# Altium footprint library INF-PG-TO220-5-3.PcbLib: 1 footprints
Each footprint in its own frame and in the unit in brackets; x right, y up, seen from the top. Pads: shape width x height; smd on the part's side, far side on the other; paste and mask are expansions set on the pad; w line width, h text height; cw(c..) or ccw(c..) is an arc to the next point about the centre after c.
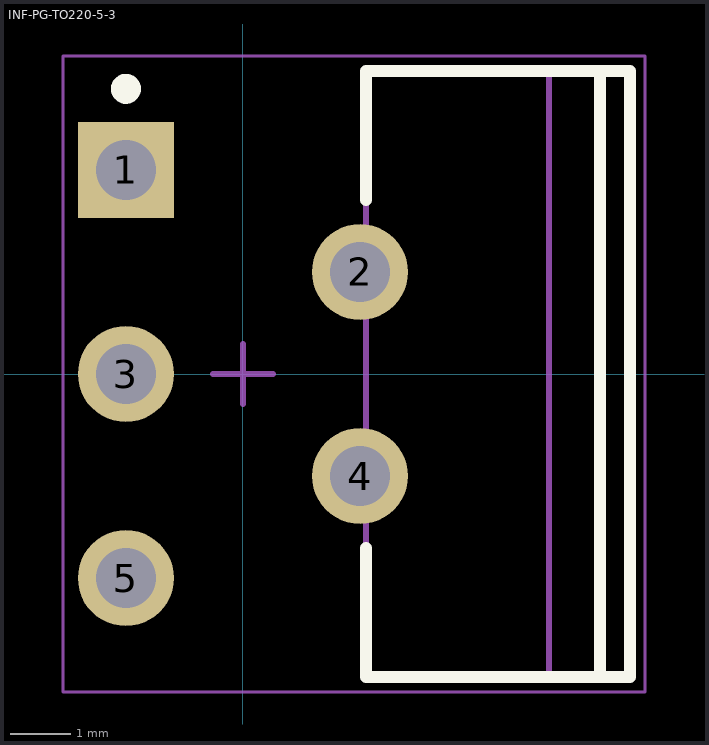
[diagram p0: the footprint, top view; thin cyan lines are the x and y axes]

## INF-PG-TO220-5-3 [mm] "FM, 5-Leads, Body 9.9x4.4mm, Pitch 1.7mm"
height 19.57
pads (5):
  rect 1.6x1.6 hole 1: 1(-1.95,3.4)
  round 1.6 hole 1: 2(1.95,1.7) 3(-1.95,0) 4(1.95,-1.7) 5(-1.95,-3.4)
Top Overlay:
  circle w0.25: c-1.95,4.75 r0.125
  lines w0.2: 2.05,-2.9 2.05,-5.05 6.45,-5.05 6.45,5.05 2.05,5.05 2.05,2.9 ; 5.95,-5.05 5.95,5.05
Mechanical 13:
  lines w0.1: 5.1,-5.05 5.1,5.05 ; 2.05,-5.05 6.45,-5.05 6.45,5.05 2.05,5.05 2.05,-5.05
Mechanical 15:
  lines w0.05: -3,-5.3 6.7,-5.3 6.7,5.3 -3,5.3 -3,-5.3
  lines w0.1: -0.5,0 0.5,0 ; 0,-0.5 0,0.5
3D body: height 19.57, standoff 18.6, extent 5.1,-4.95 6.45,4.95
3D body: height 17.13, standoff 16.77, extent 5.1,-4.95 6.45,-1.825
3D body: height 17.13, standoff 16.77, extent 5.1,1.825 6.45,4.95
3D body: height 16.77, standoff 16.41, extent 5.1,-4.95 6.45,-1.825
3D body: height 16.77, standoff 16.41, extent 5.1,1.825 6.45,4.95
3D body: height 17.47, standoff 17.13, extent 5.1,-4.95 6.45,-1.79
3D body: height 17.47, standoff 17.13, extent 5.1,1.79 6.45,4.95
3D body: height 16.42, standoff 16.07, extent 5.1,-4.95 6.45,-1.79
3D body: height 16.42, standoff 16.07, extent 5.1,1.79 6.45,4.95
3D body: height 17.79, standoff 17.47, extent 5.1,-4.95 6.45,-1.686
3D body: height 17.79, standoff 17.47, extent 5.1,1.686 6.45,4.95
3D body: height 16.08, standoff 15.76, extent 5.1,-4.95 6.45,-1.686
3D body: height 16.08, standoff 15.76, extent 5.1,1.686 6.45,4.95
3D body: height 18.07, standoff 17.78, extent 5.1,-4.95 6.45,-1.517
3D body: height 18.07, standoff 17.78, extent 5.1,1.517 6.45,4.95
3D body: height 15.76, standoff 15.48, extent 5.1,-4.95 6.45,-1.517
3D body: height 15.76, standoff 15.48, extent 5.1,1.517 6.45,4.95
3D body: height 18.29, standoff 18.06, extent 5.1,-4.95 6.45,-1.29
3D body: height 18.29, standoff 18.06, extent 5.1,1.29 6.45,4.95
3D body: height 15.48, standoff 15.25, extent 5.1,-4.95 6.45,-1.29
3D body: height 15.48, standoff 15.25, extent 5.1,1.29 6.45,4.95
3D body: height 18.46, standoff 18.29, extent 5.1,-4.95 6.45,-1.014
3D body: height 18.46, standoff 18.29, extent 5.1,1.014 6.45,4.95
3D body: height 15.26, standoff 15.08, extent 5.1,-4.95 6.45,-1.014
3D body: height 15.26, standoff 15.08, extent 5.1,1.014 6.45,4.95
3D body: height 18.56, standoff 18.46, extent 5.1,-4.95 6.45,-0.698
3D body: height 18.56, standoff 18.46, extent 5.1,0.698 6.45,4.95
3D body: height 15.09, standoff 14.98, extent 5.1,-4.95 6.45,-0.698
3D body: height 15.09, standoff 14.98, extent 5.1,0.698 6.45,4.95
3D body: height 18.6, standoff 18.56, extent 5.1,-4.95 6.45,-0.356
3D body: height 18.6, standoff 18.56, extent 5.1,0.356 6.45,4.95
3D body: height 14.99, standoff 14.95, extent 5.1,-4.95 6.45,-0.356
3D body: height 14.99, standoff 14.95, extent 5.1,0.356 6.45,4.95
3D body: height 14.95, standoff 13.17, extent 5.1,-4.95 6.45,4.95
3D body: height 13.17, standoff 1.47, extent 2.05,-5.05 6.45,5.05
3D body: height 0, standoff -1.6, extent -2.2,-3.8 -1.7,-3
3D body: height 1.47, standoff 0.99, extent 4,-3.95 4.5,-2.85
3D body: height 0.99, standoff 0.49, extent -2.2,-3.95 4.5,-2.85
3D body: height 0.49, standoff 0, extent -2.2,-3.95 -1.7,-2.85
3D body: height 0, standoff -1.6, extent 1.7,-2.1 2.2,-1.3
3D body: height 1.47, standoff 0.99, extent 4,-2.25 4.5,-1.15
3D body: height 0.99, standoff 0.49, extent 1.7,-2.25 4.5,-1.15
3D body: height 0.49, standoff 0, extent 1.7,-2.25 2.2,-1.15
3D body: height 0, standoff -1.6, extent -2.2,-0.4 -1.7,0.4
3D body: height 1.47, standoff 0.99, extent 4,-0.55 4.5,0.55
3D body: height 0.99, standoff 0.49, extent -2.2,-0.55 4.5,0.55
3D body: height 0.49, standoff 0, extent -2.2,-0.55 -1.7,0.55
3D body: height 0, standoff -1.6, extent 1.7,1.3 2.2,2.1
3D body: height 1.47, standoff 0.99, extent 4,1.15 4.5,2.25
3D body: height 0.99, standoff 0.49, extent 1.7,1.15 4.5,2.25
3D body: height 0.49, standoff 0, extent 1.7,1.15 2.2,2.25
3D body: height 0, standoff -1.6, extent -2.2,3 -1.7,3.8
3D body: height 1.47, standoff 0.99, extent 4,2.85 4.5,3.95
3D body: height 0.99, standoff 0.49, extent -2.2,2.85 4.5,3.95
3D body: height 0.49, standoff 0, extent -2.2,2.85 -1.7,3.95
